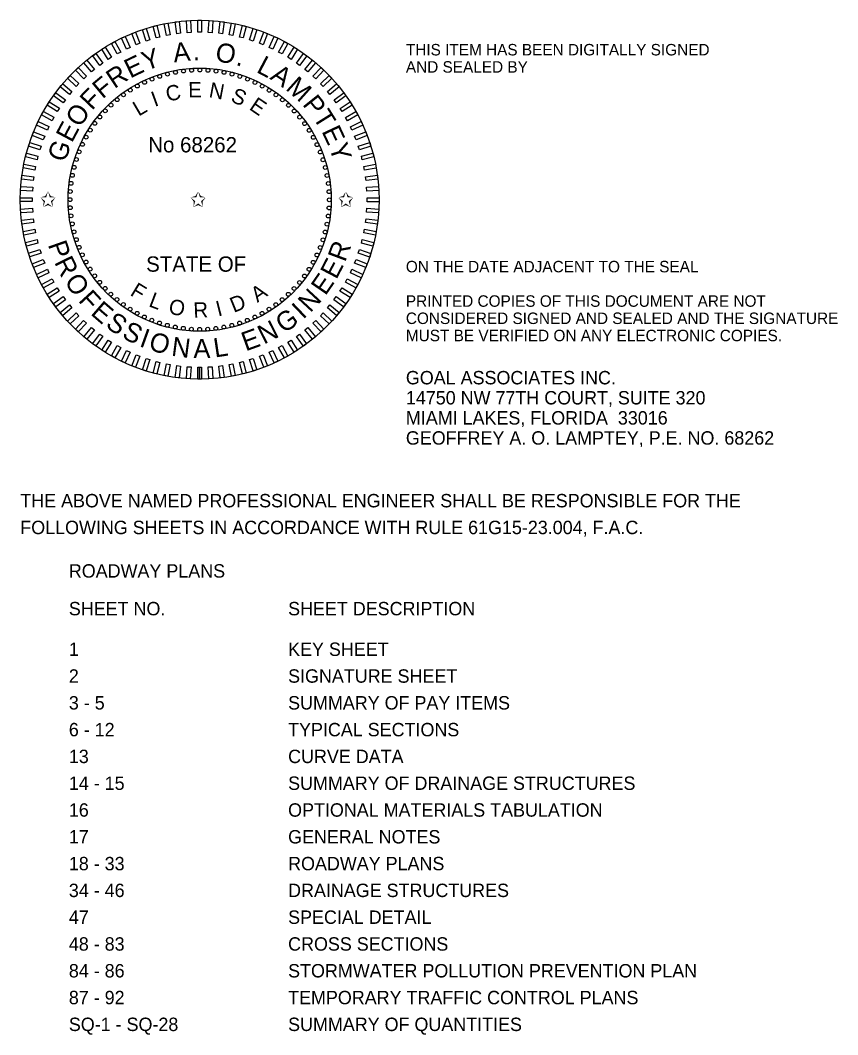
# Model space of a CAD drawing. Extents: x -811 to 10319, y -2309 to 9962.
# Drawn here: x -810.41 to -806.14, y -2184.26 to -2178.96 of the extents above; entities that cross this region are included whole.
import ezdxf

# ---------------------------------------------------------------- set-up
doc = ezdxf.new("R2010")
doc.units = 0
for name, color, linetype in [('PlotBorder_dp', 7, 'Continuous'), ('TextMinor', 7, 'Continuous'), ('TextMisc', 7, 'Continuous'), ('TextShtNo', 7, 'Continuous')]:
    doc.layers.add(name, color=color, linetype=linetype)

msp = doc.modelspace()

# ---------------------------------------------------------------- linework, layer by layer
at = {"layer": 'TextMinor'}
for radius in [0.9375, 0.6875]:
    msp.add_circle((-809.477, -2179.9009), radius, dxfattribs=at)
at = {"layer": 'TextShtNo'}
for p, q in [((-809.487, -2180.8384), (-809.4871, -2180.7759)), ((-809.477, -2180.8384), (-809.4771, -2180.7759)), ((-809.467, -2180.8383), (-809.4671, -2180.7758))]:
    msp.add_line(p, q, dxfattribs=at)
for points in [[(-809.6309, -2179.0394), (-809.6507, -2179.0432), (-809.6624, -2178.9819), (-809.6426, -2178.9781)], [(-809.5765, -2179.0315), (-809.5965, -2179.034), (-809.6044, -2178.972), (-809.5843, -2178.9695)], [(-809.5217, -2179.0269), (-809.5419, -2179.0282), (-809.5458, -2178.9659), (-809.5256, -2178.9646)], [(-809.4668, -2179.0258), (-809.487, -2179.0258), (-809.487, -2178.9634), (-809.4668, -2178.9634)], [(-809.4118, -2179.0282), (-809.432, -2179.0269), (-809.4281, -2178.9646), (-809.4079, -2178.9659)], [(-809.3572, -2179.034), (-809.3772, -2179.0315), (-809.3694, -2178.9695), (-809.3493, -2178.9721)], [(-809.303, -2179.0432), (-809.3228, -2179.0395), (-809.3111, -2178.9781), (-809.2913, -2178.9819)], [(-809.7896, -2179.0835), (-809.8084, -2179.091), (-809.8314, -2179.0329), (-809.8126, -2179.0255)], [(-809.7377, -2179.0655), (-809.7569, -2179.0718), (-809.7762, -2179.0124), (-809.757, -2179.0061)], [(-809.6847, -2179.0508), (-809.7042, -2179.0558), (-809.7198, -2178.9953), (-809.7002, -2178.9903)], [(-809.2495, -2179.0559), (-809.269, -2179.0508), (-809.2535, -2178.9904), (-809.2339, -2178.9954)], [(-809.1969, -2179.0718), (-809.2161, -2179.0656), (-809.1968, -2179.0062), (-809.1776, -2179.0124)], [(-809.1454, -2179.091), (-809.1641, -2179.0836), (-809.1411, -2179.0256), (-809.1224, -2179.033)], [(-809.8896, -2179.1292), (-809.9073, -2179.1389), (-809.9373, -2179.0842), (-809.9197, -2179.0745)], [(-809.8403, -2179.1048), (-809.8586, -2179.1134), (-809.8852, -2179.0569), (-809.8669, -2179.0483)], [(-809.0952, -2179.1135), (-809.1134, -2179.1049), (-809.0868, -2179.0484), (-809.0686, -2179.057)], [(-809.0465, -2179.139), (-809.0642, -2179.1293), (-809.0341, -2179.0745), (-809.0164, -2179.0843)], [(-809.983, -2179.187), (-809.9994, -2179.1988), (-810.0361, -2179.1483), (-810.0197, -2179.1365)], [(-809.9372, -2179.1566), (-809.9543, -2179.1674), (-809.9877, -2179.1147), (-809.9707, -2179.1039)], [(-808.9995, -2179.1675), (-809.0165, -2179.1567), (-808.9831, -2179.104), (-808.966, -2179.1148)], [(-808.9544, -2179.1989), (-808.9707, -2179.1871), (-808.934, -2179.1366), (-808.9177, -2179.1484)], [(-810.0269, -2179.2202), (-810.0424, -2179.233), (-810.0822, -2179.1849), (-810.0667, -2179.172)], [(-808.9113, -2179.2331), (-808.9269, -2179.2203), (-808.8871, -2179.1722), (-808.8715, -2179.185)], [(-810.0685, -2179.256), (-810.0832, -2179.2698), (-810.126, -2179.2243), (-810.1113, -2179.2105)], [(-808.8705, -2179.27), (-808.8852, -2179.2562), (-808.8425, -2179.2106), (-808.8278, -2179.2245)], [(-810.1447, -2179.3353), (-810.1575, -2179.3508), (-810.2057, -2179.311), (-810.1928, -2179.2955)], [(-810.1078, -2179.2944), (-810.1217, -2179.3092), (-810.1672, -2179.2664), (-810.1534, -2179.2517)], [(-808.8321, -2179.3093), (-808.8459, -2179.2946), (-808.8004, -2179.2518), (-808.7866, -2179.2666)], [(-808.7962, -2179.351), (-808.8091, -2179.3354), (-808.761, -2179.2956), (-808.7481, -2179.3112)], [(-810.1789, -2179.3783), (-810.1907, -2179.3946), (-810.2413, -2179.3579), (-810.2294, -2179.3416)], [(-808.763, -2179.3948), (-808.7749, -2179.3784), (-808.7244, -2179.3417), (-808.7125, -2179.3581)], [(-810.2103, -2179.4234), (-810.2211, -2179.4404), (-810.2738, -2179.407), (-810.263, -2179.3899)], [(-808.7327, -2179.4406), (-808.7435, -2179.4236), (-808.6908, -2179.3901), (-808.68, -2179.4071)], [(-810.2388, -2179.4704), (-810.2486, -2179.4881), (-810.3033, -2179.458), (-810.2936, -2179.4403)], [(-808.7052, -2179.4882), (-808.715, -2179.4706), (-808.6603, -2179.4405), (-808.6505, -2179.4582)], [(-810.2644, -2179.5191), (-810.273, -2179.5373), (-810.3295, -2179.5108), (-810.3209, -2179.4925)], [(-808.6809, -2179.5375), (-808.6895, -2179.5193), (-808.633, -2179.4927), (-808.6244, -2179.5109)], [(-810.2868, -2179.5693), (-810.2942, -2179.588), (-810.3523, -2179.5651), (-810.3448, -2179.5463)], [(-808.6596, -2179.5882), (-808.667, -2179.5695), (-808.609, -2179.5465), (-808.6016, -2179.5652)], [(-810.306, -2179.6208), (-810.3122, -2179.64), (-810.3716, -2179.6207), (-810.3654, -2179.6015)], [(-808.6416, -2179.6402), (-808.6478, -2179.621), (-808.5885, -2179.6017), (-808.5822, -2179.6209)], [(-810.322, -2179.6734), (-810.327, -2179.6929), (-810.3875, -2179.6774), (-810.3824, -2179.6579)], [(-808.6269, -2179.6931), (-808.6319, -2179.6736), (-808.5714, -2179.658), (-808.5664, -2179.6776)], [(-810.3346, -2179.7269), (-810.3384, -2179.7467), (-810.3997, -2179.735), (-810.3959, -2179.7152)], [(-808.6155, -2179.7469), (-808.6193, -2179.7271), (-808.558, -2179.7154), (-808.5542, -2179.7352)], [(-810.3438, -2179.7811), (-810.3463, -2179.8011), (-810.4083, -2179.7933), (-810.4058, -2179.7733)], [(-808.6075, -2179.8013), (-808.6101, -2179.7813), (-808.5481, -2179.7735), (-808.5456, -2179.7935)], [(-810.3496, -2179.8358), (-810.3509, -2179.8559), (-810.4132, -2179.852), (-810.4119, -2179.8318)], [(-808.603, -2179.8561), (-808.6043, -2179.8359), (-808.542, -2179.832), (-808.5407, -2179.8522)], [(-810.352, -2179.8907), (-810.352, -2179.9109), (-810.4144, -2179.9109), (-810.4144, -2179.8907)], [(-808.6019, -2179.9111), (-808.6019, -2179.8909), (-808.5395, -2179.8909), (-808.5395, -2179.9111)], [(-810.3509, -2179.9456), (-810.3496, -2179.9658), (-810.4119, -2179.9697), (-810.4132, -2179.9496)], [(-808.6043, -2179.966), (-808.603, -2179.9458), (-808.5407, -2179.9498), (-808.542, -2179.9699)], [(-810.3464, -2180.0004), (-810.3438, -2180.0205), (-810.4058, -2180.0283), (-810.4083, -2180.0083)], [(-808.6101, -2180.0206), (-808.6076, -2180.0006), (-808.5456, -2180.0084), (-808.5481, -2180.0285)], [(-810.3384, -2180.0548), (-810.3346, -2180.0747), (-810.3959, -2180.0864), (-810.3997, -2180.0665)], [(-808.6193, -2180.0748), (-808.6155, -2180.055), (-808.5542, -2180.0667), (-808.558, -2180.0865)], [(-810.327, -2180.1086), (-810.322, -2180.1282), (-810.3825, -2180.1437), (-810.3875, -2180.1241)], [(-808.6319, -2180.1283), (-808.6269, -2180.1088), (-808.5664, -2180.1243), (-808.5715, -2180.1439)], [(-810.3123, -2180.1616), (-810.3061, -2180.1808), (-810.3654, -2180.2001), (-810.3717, -2180.1809)], [(-808.6479, -2180.181), (-808.6417, -2180.1618), (-808.5823, -2180.1811), (-808.5885, -2180.2003)], [(-810.2943, -2180.2135), (-810.2869, -2180.2323), (-810.3449, -2180.2553), (-810.3523, -2180.2365)], [(-808.6671, -2180.2325), (-808.6597, -2180.2137), (-808.6016, -2180.2367), (-808.6091, -2180.2554)], [(-810.273, -2180.2642), (-810.2644, -2180.2825), (-810.3209, -2180.3091), (-810.3295, -2180.2908)], [(-808.6895, -2180.2827), (-808.6809, -2180.2644), (-808.6244, -2180.291), (-808.633, -2180.3092)], [(-810.2487, -2180.3135), (-810.2389, -2180.3312), (-810.2936, -2180.3613), (-810.3034, -2180.3436)], [(-810.2212, -2180.3611), (-810.2104, -2180.3782), (-810.2631, -2180.4116), (-810.2739, -2180.3946)], [(-808.7436, -2180.3783), (-808.7328, -2180.3613), (-808.6801, -2180.3947), (-808.6909, -2180.4118)], [(-808.7151, -2180.3313), (-808.7053, -2180.3137), (-808.6506, -2180.3437), (-808.6603, -2180.3614)], [(-810.1909, -2180.407), (-810.179, -2180.4233), (-810.2295, -2180.46), (-810.2414, -2180.4437)], [(-808.775, -2180.4234), (-808.7632, -2180.4071), (-808.7126, -2180.4438), (-808.7245, -2180.4601)], [(-810.1577, -2180.4508), (-810.1448, -2180.4663), (-810.1929, -2180.5061), (-810.2058, -2180.4906)], [(-808.8092, -2180.4665), (-808.7964, -2180.4509), (-808.7482, -2180.4907), (-808.7611, -2180.5063)], [(-810.1218, -2180.4924), (-810.108, -2180.5072), (-810.1535, -2180.5499), (-810.1673, -2180.5352)], [(-808.8461, -2180.5073), (-808.8322, -2180.4926), (-808.7867, -2180.5353), (-808.8005, -2180.55)], [(-810.0834, -2180.5318), (-810.0687, -2180.5456), (-810.1114, -2180.5911), (-810.1261, -2180.5773)], [(-810.0426, -2180.5686), (-810.027, -2180.5815), (-810.0668, -2180.6296), (-810.0824, -2180.6167)], [(-808.927, -2180.5816), (-808.9115, -2180.5687), (-808.8717, -2180.6168), (-808.8872, -2180.6297)], [(-808.8854, -2180.5457), (-808.8707, -2180.5319), (-808.8279, -2180.5774), (-808.8426, -2180.5912)], [(-809.9995, -2180.6028), (-809.9832, -2180.6147), (-810.0199, -2180.6652), (-810.0362, -2180.6533)], [(-808.9709, -2180.6148), (-808.9545, -2180.6029), (-808.9178, -2180.6534), (-808.9342, -2180.6653)], [(-809.9544, -2180.6342), (-809.9374, -2180.645), (-809.9708, -2180.6978), (-809.9879, -2180.6869)], [(-809.9074, -2180.6628), (-809.8897, -2180.6725), (-809.9198, -2180.7272), (-809.9375, -2180.7175)], [(-809.0643, -2180.6726), (-809.0466, -2180.6628), (-809.0166, -2180.7176), (-809.0342, -2180.7273)], [(-809.0167, -2180.6451), (-808.9996, -2180.6343), (-808.9662, -2180.687), (-808.9832, -2180.6979)], [(-809.8587, -2180.6883), (-809.8405, -2180.6969), (-809.8671, -2180.7534), (-809.8853, -2180.7448)], [(-809.8085, -2180.7107), (-809.7898, -2180.7181), (-809.8128, -2180.7762), (-809.8315, -2180.7688)], [(-809.757, -2180.7299), (-809.7378, -2180.7362), (-809.7571, -2180.7955), (-809.7763, -2180.7893)], [(-809.2162, -2180.7362), (-809.197, -2180.73), (-809.1777, -2180.7894), (-809.1969, -2180.7956)], [(-809.1643, -2180.7182), (-809.1455, -2180.7108), (-809.1225, -2180.7688), (-809.1413, -2180.7763)], [(-809.1136, -2180.697), (-809.0953, -2180.6884), (-809.0687, -2180.7449), (-809.087, -2180.7535)], [(-809.7044, -2180.7459), (-809.6849, -2180.7509), (-809.7004, -2180.8114), (-809.72, -2180.8064)], [(-809.6509, -2180.7585), (-809.6311, -2180.7623), (-809.6428, -2180.8236), (-809.6626, -2180.8198)], [(-809.5967, -2180.7677), (-809.5767, -2180.7703), (-809.5845, -2180.8322), (-809.6046, -2180.8297)], [(-809.5421, -2180.7735), (-809.5219, -2180.7748), (-809.5258, -2180.8371), (-809.546, -2180.8358)], [(-809.4871, -2180.7759), (-809.467, -2180.7759), (-809.467, -2180.8383), (-809.4871, -2180.8383)], [(-809.4322, -2180.7748), (-809.412, -2180.7735), (-809.4081, -2180.8359), (-809.4283, -2180.8371)], [(-809.3774, -2180.7703), (-809.3574, -2180.7677), (-809.3495, -2180.8297), (-809.3696, -2180.8322)], [(-809.323, -2180.7623), (-809.3032, -2180.7585), (-809.2915, -2180.8199), (-809.3113, -2180.8236)], [(-809.2692, -2180.7509), (-809.2497, -2180.7459), (-809.2341, -2180.8064), (-809.2537, -2180.8114)]]:
    msp.add_lwpolyline(points, close=True, dxfattribs=at)
for centre in [(-809.6858, -2179.2564), (-809.6449, -2179.2445), (-809.6033, -2179.2353), (-809.5613, -2179.2287), (-809.5189, -2179.2247), (-809.4764, -2179.2234), (-809.4338, -2179.2248), (-809.3915, -2179.2288), (-809.3495, -2179.2355), (-809.3079, -2179.2448), (-809.2671, -2179.2567), (-809.8028, -2179.3069), (-809.7649, -2179.2876), (-809.7258, -2179.2708), (-809.227, -2179.2712), (-809.188, -2179.2881), (-809.1501, -2179.3075), (-809.8747, -2179.3525), (-809.8395, -2179.3286), (-809.1135, -2179.3292), (-809.0783, -2179.3531), (-809.9403, -2179.4066), (-809.9084, -2179.3785), (-809.0447, -2179.3792), (-809.0128, -2179.4074), (-809.9986, -2179.4686), (-809.9704, -2179.4367), (-808.9827, -2179.4375), (-808.9546, -2179.4695), (-810.0247, -2179.5022), (-808.9285, -2179.5031), (-810.0703, -2179.574), (-810.0487, -2179.5374), (-808.9046, -2179.5383), (-808.883, -2179.575), (-810.0897, -2179.6119), (-808.8637, -2179.6129), (-810.1066, -2179.651), (-808.8468, -2179.652), (-810.133, -2179.7318), (-810.1211, -2179.691), (-808.8325, -2179.6921), (-808.8206, -2179.7329), (-810.1423, -2179.7734), (-808.8114, -2179.7745), (-810.149, -2179.8154), (-808.8048, -2179.8165), (-810.153, -2179.8578), (-808.8008, -2179.8589), (-810.1544, -2179.9003), (-810.1531, -2179.9428), (-808.8009, -2179.944), (-808.7995, -2179.9014), (-810.1491, -2179.9852), (-808.8049, -2179.9863), (-810.1425, -2180.0273), (-808.8116, -2180.0284), (-810.1333, -2180.0688), (-810.1214, -2180.1097), (-808.8209, -2180.0699), (-810.1071, -2180.1497), (-808.8473, -2180.1508), (-808.8328, -2180.1108), (-810.0902, -2180.1888), (-808.8642, -2180.1898), (-810.0709, -2180.2267), (-810.0493, -2180.2634), (-808.9052, -2180.2644), (-808.8836, -2180.2277), (-810.0254, -2180.2986), (-808.9292, -2180.2995), (-809.9993, -2180.3323), (-809.9712, -2180.3642), (-808.9835, -2180.365), (-808.9553, -2180.3331), (-809.9411, -2180.3943), (-809.9092, -2180.4225), (-809.0456, -2180.4232), (-809.0136, -2180.3951), (-809.8756, -2180.4486), (-809.8404, -2180.4726), (-809.1144, -2180.4732), (-809.0792, -2180.4493), (-809.8038, -2180.4943), (-809.7659, -2180.5136), (-809.7269, -2180.5306), (-809.2281, -2180.531), (-809.189, -2180.5141), (-809.1511, -2180.4948), (-809.6868, -2180.545), (-809.646, -2180.5569), (-809.6044, -2180.5662), (-809.5624, -2180.5729), (-809.5201, -2180.577), (-809.477, -2180.5784), (-809.435, -2180.577), (-809.3926, -2180.5731), (-809.3506, -2180.5664), (-809.309, -2180.5572), (-809.2681, -2180.5454)]:
    msp.add_circle(centre, 0.01, dxfattribs=at)

# ---------------------------------------------------------------- texts
at = {"layer": 'PlotBorder_dp'}
for s, height, p in [('THIS ITEM HAS BEEN DIGITALLY SIGNED ', 0.06, (-808.3993, -2179.147)), ('AND SEALED BY', 0.06, (-808.3993, -2179.237)), ('ON THE DATE ADJACENT TO THE SEAL', 0.06, (-808.3993, -2180.2804)), ('PRINTED COPIES OF THIS DOCUMENT ARE NOT ', 0.06, (-808.3993, -2180.4604)), ('CONSIDERED SIGNED AND SEALED AND THE SIGNATURE ', 0.06, (-808.3993, -2180.5504)), ('MUST BE VERIFIED ON ANY ELECTRONIC COPIES.', 0.06, (-808.3993, -2180.6404)), ('GOAL ASSOCIATES INC.', 0.07, (-808.3993, -2180.8657)), ('14750 NW 77TH COURT, SUITE 320', 0.07, (-808.3993, -2180.9707)), ('MIAMI LAKES, FLORIDA  33016', 0.07, (-808.3993, -2181.0757)), ('GEOFFREY A. O. LAMPTEY, P.E. NO. 68262', 0.07, (-808.3993, -2181.1807)), ('THE ABOVE NAMED PROFESSIONAL ENGINEER SHALL BE RESPONSIBLE FOR THE ', 0.07, (-810.4145, -2181.5084)), ('FOLLOWING SHEETS IN ACCORDANCE WITH RULE 61G15-23.004, F.A.C.', 0.07, (-810.4145, -2181.6484)), ('ROADWAY PLANS', 0.07, (-810.1607, -2181.8755))]:
    msp.add_text(s, height=height, dxfattribs=at).set_placement(p)
at = {"layer": 'TextMisc'}
for s, p in [('SHEET NO.', (-810.1607, -2182.0725)), ('SHEET DESCRIPTION', (-809.0148, -2182.0725)), ('1', (-810.1607, -2182.2847)), ('KEY SHEET', (-809.0148, -2182.2847)), ('2', (-810.1607, -2182.4247)), ('SIGNATURE SHEET', (-809.0148, -2182.4247)), ('3 - 5', (-810.1607, -2182.5647)), ('SUMMARY OF PAY ITEMS', (-809.0148, -2182.5647)), ('6 - 12', (-810.1607, -2182.7047)), ('TYPICAL SECTIONS', (-809.0148, -2182.7047)), ('13', (-810.1607, -2182.8447)), ('CURVE DATA', (-809.0148, -2182.8447)), ('14 - 15', (-810.1607, -2182.9847)), ('SUMMARY OF DRAINAGE STRUCTURES', (-809.0148, -2182.9847)), ('16', (-810.1607, -2183.1247)), ('OPTIONAL MATERIALS TABULATION', (-809.0148, -2183.1247)), ('17', (-810.1607, -2183.2647)), ('GENERAL NOTES', (-809.0148, -2183.2647)), ('18 - 33', (-810.1607, -2183.4047)), ('ROADWAY PLANS', (-809.0148, -2183.4047)), ('34 - 46', (-810.1607, -2183.5447)), ('DRAINAGE STRUCTURES', (-809.0148, -2183.5447)), ('47', (-810.1607, -2183.6847)), ('SPECIAL DETAIL', (-809.0148, -2183.6847)), ('48 - 83', (-810.1607, -2183.8247)), ('CROSS SECTIONS', (-809.0148, -2183.8247)), ('84 - 86', (-810.1607, -2183.9647)), ('STORMWATER POLLUTION PREVENTION PLAN', (-809.0148, -2183.9647)), ('87 - 92', (-810.1607, -2184.1047)), ('TEMPORARY TRAFFIC CONTROL PLANS', (-809.0148, -2184.1047)), ('SQ-1 - SQ-28', (-810.1607, -2184.2447)), ('SUMMARY OF QUANTITIES', (-809.0148, -2184.2447))]:
    msp.add_text(s, height=0.07, dxfattribs=at).set_placement(p)
at = {"layer": 'TextShtNo'}
for s, height, rotation, p in [('A', 0.1, 6.3024, (-809.6107, -2179.1837)), ('O', 0.1, 349.6813, (-809.3999, -2179.1754)), ('E', 0.1, 25.5991, (-809.8401, -2179.2682)), ('Y', 0.1, 18.5568, (-809.7598, -2179.2284)), ('.', 0.1, 358.5354, (-809.5125, -2179.1722)), ('.', 0.1, 341.0204, (-809.2916, -2179.1953)), ('L', 0.1, 332.1663, (-809.1852, -2179.2322)), ('F', 0.1, 39.8708, (-809.9849, -2179.3773)), ('R', 0.1, 33.4204, (-809.9229, -2179.3235)), ('A', 0.1, 325.9031, (-809.114, -2179.2681)), ('C', 0.08, 12.2025, (-809.6447, -2179.3893)), ('E', 0.08, 0.4186, (-809.5367, -2179.3658)), ('N', 0.08, 349.2914, (-809.4323, -2179.3643)), ('M', 0.1, 318.1361, (-809.0318, -2179.3229)), ('F', 0.1, 46.3211, (-810.0405, -2179.4376)), ('I', 0.08, 20.0117, (-809.7126, -2179.4168)), ('S', 0.08, 337.0221, (-809.3193, -2179.3861)), ('P', 0.1, 308.6901, (-808.943, -2179.4038)), ('O', 0.1, 54.982, (-810.1038, -2179.5278)), ('L', 0.08, 30.4021, (-809.7961, -2179.4672)), ('E', 0.08, 325.8663, (-809.2227, -2179.4263)), ('T', 0.1, 301.9499, (-808.8883, -2179.4699)), ('E', 0.1, 62.0242, (-810.1449, -2179.6074)), ('E', 0.1, 295.1251, (-808.8413, -2179.5429)), ('G', 0.1, 70.5583, (-810.181, -2179.7098)), ('Y', 0.1, 288.0828, (-808.8022, -2179.6236)), ('P', 0.1, 289.4055, (-810.2717, -2180.1354)), ('R', 0.1, 69.5134, (-808.7168, -2180.2306)), ('R', 0.1, 296.1458, (-810.2386, -2180.2271)), ('E', 0.1, 62.4712, (-808.7629, -2180.3213)), ('O', 0.1, 303.9671, (-810.1872, -2180.3277)), ('E', 0.1, 55.4289, (-808.8198, -2180.4057)), ('F', 0.08, 328.7241, (-809.845, -2180.3975)), ('A', 0.08, 34.4992, (-809.1751, -2180.4403)), ('N', 0.1, 47.1788, (-808.8991, -2180.4947)), ('F', 0.1, 312.628, (-810.1148, -2180.4298)), ('L', 0.08, 339.2916, (-809.7477, -2180.4565)), ('D', 0.08, 22.0128, (-809.2989, -2180.4928)), ('E', 0.1, 319.0783, (-810.0513, -2180.4981)), ('O', 0.08, 349.6821, (-809.643, -2180.4962)), ('R', 0.08, 2.3398, (-809.5085, -2180.5182)), ('I', 0.08, 14.2037, (-809.381, -2180.5115)), ('I', 0.1, 43.6456, (-808.9368, -2180.5292)), ('S', 0.1, 326.1206, (-809.9738, -2180.564)), ('G', 0.1, 35.1115, (-809.036, -2180.6024)), ('S', 0.1, 333.193, (-809.8883, -2180.6201)), ('I', 0.1, 340.2654, (-809.7966, -2180.6653)), ('E', 0.1, 19.8191, (-809.2366, -2180.6939)), ('N', 0.1, 26.8614, (-809.1412, -2180.6584)), ('O', 0.1, 343.7986, (-809.7489, -2180.6836)), ('N', 0.1, 352.4595, (-809.628, -2180.7156)), ('A', 0.1, 0.7097, (-809.5095, -2180.7288)), ('L', 0.1, 8.4767, (-809.3973, -2180.7256))]:
    msp.add_text(s, height=height, rotation=rotation, dxfattribs=at).set_placement(p)
for s, p in [('No 68262', (-809.7459, -2179.6536)), ('✩', (-810.3119, -2179.9388)), ('✩', (-809.5272, -2179.9388)), ('✩', (-808.7554, -2179.9388)), ('STATE OF', (-809.7567, -2180.2771))]:
    msp.add_text(s, height=0.08, dxfattribs=at).set_placement(p)

doc.saveas('drawing.dxf')
